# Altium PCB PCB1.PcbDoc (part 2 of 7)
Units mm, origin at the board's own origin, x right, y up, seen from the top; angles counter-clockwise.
Board outline 139.9 x 46.81 mm, 2 copper layers (Top Layer, Bottom Layer); 0 components, 100 nets, 100 pads, 0 vias.
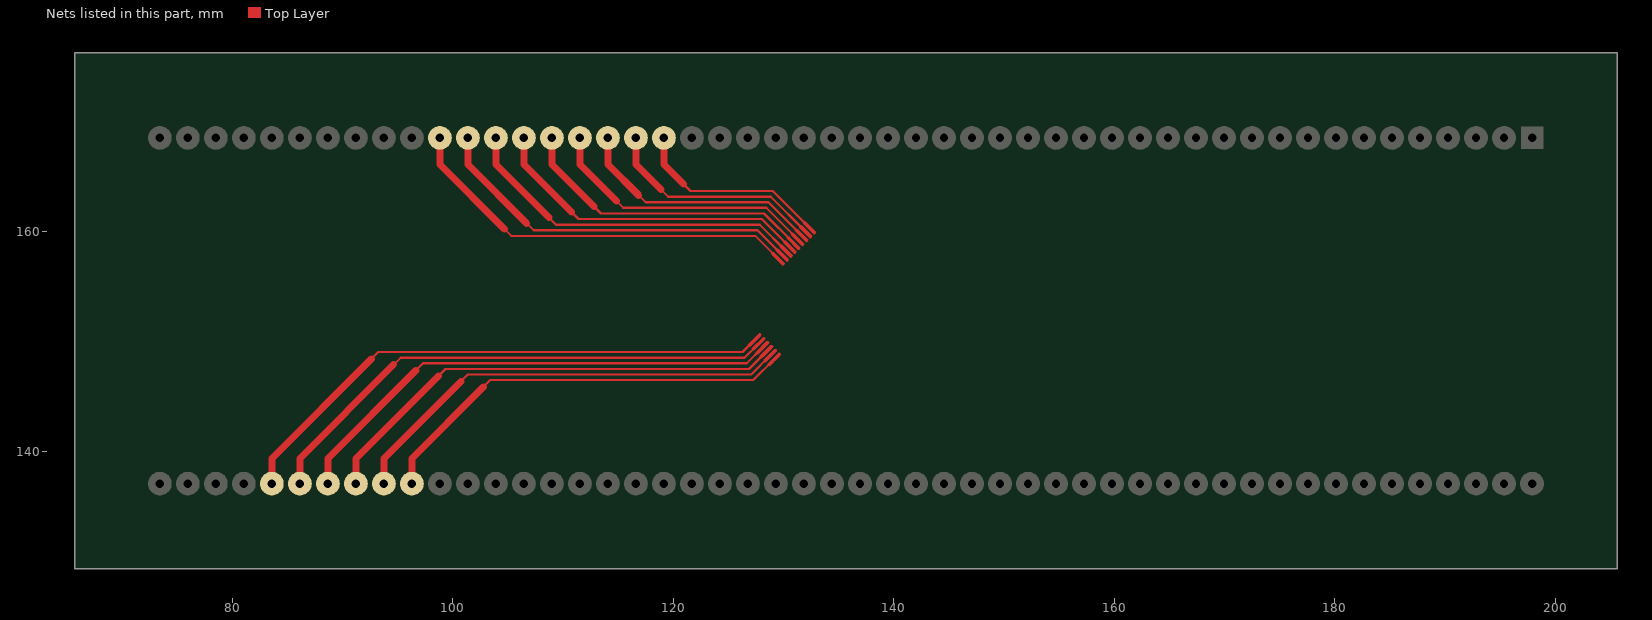
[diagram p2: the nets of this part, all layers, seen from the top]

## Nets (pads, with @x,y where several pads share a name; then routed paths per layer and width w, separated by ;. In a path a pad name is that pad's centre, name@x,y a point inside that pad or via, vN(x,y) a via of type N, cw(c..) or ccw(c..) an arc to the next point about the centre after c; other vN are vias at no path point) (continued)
$Net14: pad.1@83.587,137.086 | length 74.5
  Top Layer w0.03: 126.815,149.679 127.072,149.679 ; 126.815,149.694 127.087,149.694 ; 126.818,149.71 127.102,149.71 ; 126.82,149.664 127.057,149.664 ; 126.828,149.649 127.041,149.649 ; 126.838,149.633 127.026,149.633 ; 126.843,149.755 127.148,149.755 ; 126.851,149.618 127.011,149.618 ; 126.859,149.771 127.163,149.771 ; 126.866,149.603 126.996,149.603 ; 126.874,149.786 127.179,149.786 ; 126.889,149.588 126.978,149.588 ; 126.889,149.801 127.194,149.801 ; 126.904,149.816 127.209,149.816 ; 126.919,149.831 127.224,149.831 ; 126.935,149.847 127.24,149.847 ; 126.95,149.862 127.255,149.862 ; 126.965,149.877 127.27,149.877 ; 126.98,149.892 127.285,149.892 ; 126.996,149.908 127.3,149.908 ; 127.011,149.923 127.316,149.923 ; 127.026,149.938 127.331,149.938 ; 127.041,149.953 127.346,149.953 ; 127.057,149.969 127.361,149.969 ; 127.072,149.984 127.377,149.984 ; 127.087,149.999 127.392,149.999 ; 127.102,150.014 127.407,150.014 ; 127.118,149.725 126.82,149.725 ; 127.118,150.03 127.422,150.03 ; 127.133,149.74 126.828,149.74 ; 127.133,150.045 127.438,150.045 ; 127.148,150.06 127.455,150.06 ; 127.163,150.075 127.471,150.075 ; 127.179,150.091 127.486,150.091 ; 127.194,150.106 127.501,150.106 ; 127.209,150.121 127.516,150.121 ; 127.224,150.136 127.532,150.136 ; 127.24,150.152 127.547,150.152 ; 127.255,150.167 127.562,150.167 ; 127.27,150.182 127.577,150.182 ; 127.285,150.197 127.593,150.197 ; 127.3,150.212 127.608,150.212 ; 127.318,150.228 127.623,150.228 ; 127.334,150.243 127.638,150.243 ; 127.349,150.258 127.654,150.258 ; 127.364,150.273 127.669,150.273 ; 127.379,150.289 127.684,150.289 ; 127.394,150.304 127.699,150.304 ; 127.41,150.319 127.715,150.319 ; 127.425,150.334 127.73,150.334 ; 127.44,150.35 127.745,150.35 ; 127.455,150.365 127.76,150.365 ; 127.471,150.38 127.775,150.38 ; 127.486,150.395 127.791,150.395 ; 127.501,150.411 127.806,150.411 ; 127.516,150.426 127.821,150.426 ; 127.532,150.441 127.836,150.441 ; 127.547,150.456 127.852,150.456 ; 127.562,150.472 127.867,150.472 ; 127.577,150.487 127.882,150.487 ; 127.593,150.502 127.897,150.502 ; 127.608,150.517 127.913,150.517 ; 127.623,150.533 127.928,150.533 ; 127.638,150.548 127.938,150.548 ; 127.654,150.563 127.946,150.563 ; 127.669,150.578 127.948,150.578 ; 127.684,150.593 127.951,150.593 ; 127.699,150.609 127.948,150.609 ; 127.715,150.624 127.943,150.624 ; 127.73,150.639 127.933,150.639 ; 127.745,150.654 127.923,150.654 ; 127.76,150.67 127.908,150.67 ; 127.775,150.685 127.892,150.685 ; 127.796,150.7 127.869,150.7 ; 126.82,149.725 126.828,149.74 ; 126.82,149.725 126.813,149.692 126.815,149.674 126.82,149.659 126.841,149.628 126.869,149.6 126.899,149.58 126.914,149.575 126.932,149.572 126.965,149.58 126.978,149.588 ; 126.828,149.74 126.838,149.753 127.786,150.695 127.798,150.703 127.831,150.71 127.849,150.708 127.864,150.703 127.895,150.682 127.923,150.654 ; 126.978,149.588 127.925,150.53 127.935,150.543 127.943,150.558 127.951,150.591 127.948,150.609 ; 127.923,150.654 127.943,150.624 ; 127.943,150.624 127.948,150.609
  Top Layer w0.203: 92.604,148.389 93.239,149.024 126.264,149.024 127.382,150.141
  Top Layer w0.635: pad.1@83.587,137.086 83.587,139.372 92.604,148.389
$Net15: pad.1@86.127,137.086 | length 72.1
  Top Layer w0.03: 127.171,149.323 127.427,149.323 ; 127.171,149.339 127.443,149.339 ; 127.173,149.354 127.458,149.354 ; 127.176,149.308 127.412,149.308 ; 127.184,149.293 127.397,149.293 ; 127.194,149.278 127.382,149.278 ; 127.199,149.4 127.504,149.4 ; 127.207,149.263 127.367,149.263 ; 127.214,149.415 127.519,149.415 ; 127.222,149.247 127.351,149.247 ; 127.229,149.43 127.534,149.43 ; 127.245,149.232 127.334,149.232 ; 127.245,149.445 127.549,149.445 ; 127.26,149.461 127.565,149.461 ; 127.275,149.476 127.58,149.476 ; 127.29,149.491 127.595,149.491 ; 127.306,149.506 127.61,149.506 ; 127.321,149.522 127.626,149.522 ; 127.336,149.537 127.641,149.537 ; 127.351,149.552 127.656,149.552 ; 127.367,149.567 127.671,149.567 ; 127.382,149.583 127.687,149.583 ; 127.397,149.598 127.702,149.598 ; 127.412,149.613 127.717,149.613 ; 127.427,149.628 127.732,149.628 ; 127.443,149.644 127.748,149.644 ; 127.458,149.659 127.763,149.659 ; 127.473,149.369 127.176,149.369 ; 127.473,149.674 127.778,149.674 ; 127.488,149.384 127.184,149.384 ; 127.488,149.689 127.793,149.689 ; 127.504,149.704 127.811,149.704 ; 127.519,149.72 127.826,149.72 ; 127.534,149.735 127.842,149.735 ; 127.549,149.75 127.857,149.75 ; 127.565,149.765 127.872,149.765 ; 127.58,149.781 127.887,149.781 ; 127.595,149.796 127.902,149.796 ; 127.61,149.811 127.918,149.811 ; 127.626,149.826 127.933,149.826 ; 127.641,149.842 127.948,149.842 ; 127.656,149.857 127.963,149.857 ; 127.674,149.872 127.979,149.872 ; 127.689,149.887 127.994,149.887 ; 127.704,149.903 128.009,149.903 ; 127.72,149.918 128.024,149.918 ; 127.735,149.933 128.04,149.933 ; 127.75,149.948 128.055,149.948 ; 127.765,149.964 128.07,149.964 ; 127.781,149.979 128.085,149.979 ; 127.796,149.994 128.101,149.994 ; 127.811,150.009 128.116,150.009 ; 127.826,150.025 128.131,150.025 ; 127.842,150.04 128.146,150.04 ; 127.857,150.055 128.162,150.055 ; 127.872,150.07 128.177,150.07 ; 127.887,150.085 128.192,150.085 ; 127.902,150.101 128.207,150.101 ; 127.918,150.116 128.223,150.116 ; 127.933,150.131 128.238,150.131 ; 127.948,150.146 128.253,150.146 ; 127.963,150.162 128.268,150.162 ; 127.979,150.177 128.283,150.177 ; 127.994,150.192 128.294,150.192 ; 128.009,150.207 128.301,150.207 ; 128.024,150.223 128.304,150.223 ; 128.04,150.238 128.306,150.238 ; 128.055,150.253 128.304,150.253 ; 128.07,150.268 128.299,150.268 ; 128.085,150.284 128.289,150.284 ; 128.101,150.299 128.278,150.299 ; 128.116,150.314 128.263,150.314 ; 128.131,150.329 128.248,150.329 ; 128.151,150.345 128.225,150.345 ; 127.176,149.369 127.184,149.384 ; 127.176,149.369 127.168,149.336 127.171,149.318 127.176,149.303 127.196,149.273 127.224,149.245 127.255,149.224 127.27,149.219 127.288,149.217 127.321,149.224 127.334,149.232 ; 127.184,149.384 127.194,149.397 128.141,150.339 128.154,150.347 128.187,150.355 128.205,150.352 128.22,150.347 128.25,150.327 128.278,150.299 ; 127.334,149.232 128.281,150.174 128.291,150.187 128.299,150.202 128.306,150.235 128.304,150.253 ; 128.278,150.299 128.299,150.268 ; 128.299,150.268 128.304,150.253
  Top Layer w0.203: 94.636,147.881 95.271,148.516 126.465,148.516 127.737,149.786
  Top Layer w0.635: pad.1@86.127,137.086 86.127,139.372 94.636,147.881
$Net16: pad.1@88.667,137.086 | length 69.8
  Top Layer w0.03: 127.524,148.97 127.781,148.97 ; 127.524,148.986 127.796,148.986 ; 127.527,149.001 127.811,149.001 ; 127.529,148.955 127.765,148.955 ; 127.537,148.94 127.75,148.94 ; 127.547,148.925 127.735,148.925 ; 127.552,149.047 127.857,149.047 ; 127.56,148.909 127.72,148.909 ; 127.567,149.062 127.872,149.062 ; 127.575,148.894 127.704,148.894 ; 127.582,149.077 127.887,149.077 ; 127.598,148.879 127.687,148.879 ; 127.598,149.092 127.902,149.092 ; 127.613,149.108 127.918,149.108 ; 127.628,149.123 127.933,149.123 ; 127.643,149.138 127.948,149.138 ; 127.659,149.153 127.963,149.153 ; 127.674,149.169 127.979,149.169 ; 127.689,149.184 127.994,149.184 ; 127.704,149.199 128.009,149.199 ; 127.72,149.214 128.024,149.214 ; 127.735,149.229 128.04,149.229 ; 127.75,149.245 128.055,149.245 ; 127.765,149.26 128.07,149.26 ; 127.781,149.275 128.085,149.275 ; 127.796,149.29 128.101,149.29 ; 127.811,149.306 128.116,149.306 ; 127.826,149.016 127.529,149.016 ; 127.826,149.321 128.131,149.321 ; 127.842,149.031 127.537,149.031 ; 127.842,149.336 128.146,149.336 ; 127.857,149.351 128.164,149.351 ; 127.872,149.367 128.179,149.367 ; 127.887,149.382 128.195,149.382 ; 127.902,149.397 128.21,149.397 ; 127.918,149.412 128.225,149.412 ; 127.933,149.428 128.24,149.428 ; 127.948,149.443 128.256,149.443 ; 127.963,149.458 128.271,149.458 ; 127.979,149.473 128.286,149.473 ; 127.994,149.489 128.301,149.489 ; 128.009,149.504 128.316,149.504 ; 128.027,149.519 128.332,149.519 ; 128.042,149.534 128.347,149.534 ; 128.057,149.55 128.362,149.55 ; 128.073,149.565 128.377,149.565 ; 128.088,149.58 128.393,149.58 ; 128.103,149.595 128.408,149.595 ; 128.118,149.61 128.423,149.61 ; 128.134,149.626 128.438,149.626 ; 128.149,149.641 128.454,149.641 ; 128.164,149.656 128.469,149.656 ; 128.179,149.671 128.484,149.671 ; 128.195,149.687 128.499,149.687 ; 128.21,149.702 128.515,149.702 ; 128.225,149.717 128.53,149.717 ; 128.24,149.732 128.545,149.732 ; 128.256,149.748 128.56,149.748 ; 128.271,149.763 128.576,149.763 ; 128.286,149.778 128.591,149.778 ; 128.301,149.793 128.606,149.793 ; 128.316,149.809 128.621,149.809 ; 128.332,149.824 128.637,149.824 ; 128.347,149.839 128.647,149.839 ; 128.362,149.854 128.654,149.854 ; 128.377,149.87 128.657,149.87 ; 128.393,149.885 128.659,149.885 ; 128.408,149.9 128.657,149.9 ; 128.423,149.915 128.652,149.915 ; 128.438,149.931 128.642,149.931 ; 128.454,149.946 128.631,149.946 ; 128.469,149.961 128.616,149.961 ; 128.484,149.976 128.601,149.976 ; 128.504,149.991 128.578,149.991 ; 127.529,149.016 127.537,149.031 ; 127.529,149.016 127.521,148.983 127.524,148.965 127.529,148.95 127.549,148.92 127.577,148.892 127.608,148.871 127.623,148.866 127.641,148.864 127.674,148.871 127.687,148.879 ; 127.537,149.031 127.547,149.044 128.494,149.986 128.507,149.994 128.54,150.002 128.558,149.999 128.573,149.994 128.604,149.974 128.631,149.946 ; 127.687,148.879 128.634,149.821 128.644,149.834 128.652,149.849 128.659,149.882 128.657,149.9 ; 128.631,149.946 128.652,149.915 ; 128.652,149.915 128.657,149.9
  Top Layer w0.203: 96.668,147.373 97.303,148.008 126.663,148.008 128.09,149.433
  Top Layer w0.635: pad.1@88.667,137.086 88.667,139.372 96.668,147.373
$Net17: pad.1@91.207,137.086 | length 67.5
  Top Layer w0.03: 127.877,148.617 128.134,148.617 ; 127.877,148.633 128.149,148.633 ; 127.88,148.648 128.164,148.648 ; 127.882,148.602 128.118,148.602 ; 127.89,148.587 128.103,148.587 ; 127.9,148.572 128.088,148.572 ; 127.905,148.694 128.21,148.694 ; 127.913,148.556 128.073,148.556 ; 127.92,148.709 128.225,148.709 ; 127.928,148.541 128.057,148.541 ; 127.935,148.724 128.24,148.724 ; 127.951,148.526 128.04,148.526 ; 127.951,148.739 128.256,148.739 ; 127.966,148.755 128.271,148.755 ; 127.981,148.77 128.286,148.77 ; 127.996,148.785 128.301,148.785 ; 128.012,148.8 128.316,148.8 ; 128.027,148.815 128.332,148.815 ; 128.042,148.831 128.347,148.831 ; 128.057,148.846 128.362,148.846 ; 128.073,148.861 128.377,148.861 ; 128.088,148.876 128.393,148.876 ; 128.103,148.892 128.408,148.892 ; 128.118,148.907 128.423,148.907 ; 128.134,148.922 128.438,148.922 ; 128.149,148.937 128.454,148.937 ; 128.164,148.953 128.469,148.953 ; 128.179,148.663 127.882,148.663 ; 128.179,148.968 128.484,148.968 ; 128.195,148.678 127.89,148.678 ; 128.195,148.983 128.499,148.983 ; 128.21,148.998 128.517,148.998 ; 128.225,149.014 128.532,149.014 ; 128.24,149.029 128.548,149.029 ; 128.256,149.044 128.563,149.044 ; 128.271,149.059 128.578,149.059 ; 128.286,149.075 128.593,149.075 ; 128.301,149.09 128.609,149.09 ; 128.316,149.105 128.624,149.105 ; 128.332,149.12 128.639,149.12 ; 128.347,149.136 128.654,149.136 ; 128.362,149.151 128.67,149.151 ; 128.38,149.166 128.685,149.166 ; 128.395,149.181 128.7,149.181 ; 128.41,149.196 128.715,149.196 ; 128.426,149.212 128.731,149.212 ; 128.441,149.227 128.746,149.227 ; 128.456,149.242 128.761,149.242 ; 128.471,149.257 128.776,149.257 ; 128.487,149.273 128.791,149.273 ; 128.502,149.288 128.807,149.288 ; 128.517,149.303 128.822,149.303 ; 128.532,149.318 128.837,149.318 ; 128.548,149.334 128.852,149.334 ; 128.563,149.349 128.868,149.349 ; 128.578,149.364 128.883,149.364 ; 128.593,149.379 128.898,149.379 ; 128.609,149.395 128.913,149.395 ; 128.624,149.41 128.929,149.41 ; 128.639,149.425 128.944,149.425 ; 128.654,149.44 128.959,149.44 ; 128.67,149.456 128.974,149.456 ; 128.685,149.471 128.99,149.471 ; 128.7,149.486 129,149.486 ; 128.715,149.501 129.007,149.501 ; 128.731,149.517 129.01,149.517 ; 128.746,149.532 129.012,149.532 ; 128.761,149.547 129.01,149.547 ; 128.776,149.562 129.005,149.562 ; 128.791,149.577 128.995,149.577 ; 128.807,149.593 128.985,149.593 ; 128.822,149.608 128.969,149.608 ; 128.837,149.623 128.954,149.623 ; 128.858,149.638 128.931,149.638 ; 127.882,148.663 127.89,148.678 ; 127.882,148.663 127.875,148.63 127.877,148.612 127.882,148.597 127.902,148.567 127.93,148.539 127.961,148.518 127.976,148.513 127.994,148.511 128.027,148.518 128.04,148.526 ; 127.89,148.678 127.9,148.691 128.847,149.633 128.86,149.641 128.893,149.649 128.911,149.646 128.926,149.641 128.957,149.621 128.985,149.593 ; 128.04,148.526 128.987,149.468 128.997,149.481 129.005,149.496 129.012,149.529 129.01,149.547 ; 128.985,149.593 129.005,149.562 ; 129.005,149.562 129.01,149.547
  Top Layer w0.203: 98.7,146.865 99.335,147.5 126.864,147.5 128.443,149.08
  Top Layer w0.635: pad.1@91.207,137.086 91.207,139.372 98.7,146.865
$Net18: pad.1@93.747,137.086 | length 65.1
  Top Layer w0.03: 128.23,148.264 128.487,148.264 ; 128.23,148.28 128.502,148.28 ; 128.233,148.295 128.517,148.295 ; 128.235,148.249 128.471,148.249 ; 128.243,148.234 128.456,148.234 ; 128.253,148.219 128.441,148.219 ; 128.258,148.34 128.563,148.34 ; 128.266,148.203 128.426,148.203 ; 128.273,148.356 128.578,148.356 ; 128.281,148.188 128.41,148.188 ; 128.289,148.371 128.593,148.371 ; 128.304,148.173 128.393,148.173 ; 128.304,148.386 128.609,148.386 ; 128.319,148.401 128.624,148.401 ; 128.334,148.417 128.639,148.417 ; 128.35,148.432 128.654,148.432 ; 128.365,148.447 128.67,148.447 ; 128.38,148.462 128.685,148.462 ; 128.395,148.478 128.7,148.478 ; 128.41,148.493 128.715,148.493 ; 128.426,148.508 128.731,148.508 ; 128.441,148.523 128.746,148.523 ; 128.456,148.539 128.761,148.539 ; 128.471,148.554 128.776,148.554 ; 128.487,148.569 128.791,148.569 ; 128.502,148.584 128.807,148.584 ; 128.517,148.6 128.822,148.6 ; 128.532,148.31 128.235,148.31 ; 128.532,148.615 128.837,148.615 ; 128.548,148.325 128.243,148.325 ; 128.548,148.63 128.852,148.63 ; 128.563,148.645 128.87,148.645 ; 128.578,148.661 128.885,148.661 ; 128.593,148.676 128.901,148.676 ; 128.609,148.691 128.916,148.691 ; 128.624,148.706 128.931,148.706 ; 128.639,148.721 128.946,148.721 ; 128.654,148.737 128.962,148.737 ; 128.67,148.752 128.977,148.752 ; 128.685,148.767 128.992,148.767 ; 128.7,148.782 129.007,148.782 ; 128.715,148.798 129.023,148.798 ; 128.733,148.813 129.038,148.813 ; 128.748,148.828 129.053,148.828 ; 128.764,148.843 129.068,148.843 ; 128.779,148.859 129.084,148.859 ; 128.794,148.874 129.099,148.874 ; 128.809,148.889 129.114,148.889 ; 128.824,148.904 129.129,148.904 ; 128.84,148.92 129.145,148.92 ; 128.855,148.935 129.16,148.935 ; 128.87,148.95 129.175,148.95 ; 128.885,148.965 129.19,148.965 ; 128.901,148.981 129.205,148.981 ; 128.916,148.996 129.221,148.996 ; 128.931,149.011 129.236,149.011 ; 128.946,149.026 129.251,149.026 ; 128.962,149.042 129.266,149.042 ; 128.977,149.057 129.282,149.057 ; 128.992,149.072 129.297,149.072 ; 129.007,149.087 129.312,149.087 ; 129.023,149.102 129.327,149.102 ; 129.038,149.118 129.343,149.118 ; 129.053,149.133 129.353,149.133 ; 129.068,149.148 129.36,149.148 ; 129.084,149.163 129.363,149.163 ; 129.099,149.179 129.366,149.179 ; 129.114,149.194 129.363,149.194 ; 129.129,149.209 129.358,149.209 ; 129.145,149.224 129.348,149.224 ; 129.16,149.24 129.338,149.24 ; 129.175,149.255 129.322,149.255 ; 129.19,149.27 129.307,149.27 ; 129.211,149.285 129.284,149.285 ; 128.235,148.31 128.243,148.325 ; 128.235,148.31 128.228,148.277 128.23,148.259 128.235,148.244 128.256,148.213 128.283,148.186 128.314,148.165 128.329,148.16 128.347,148.158 128.38,148.165 128.393,148.173 ; 128.243,148.325 128.253,148.338 129.2,149.28 129.213,149.288 129.246,149.296 129.264,149.293 129.279,149.288 129.31,149.268 129.338,149.24 ; 128.393,148.173 129.34,149.115 129.35,149.128 129.358,149.143 129.366,149.176 129.363,149.194 ; 129.338,149.24 129.358,149.209 ; 129.358,149.209 129.363,149.194
  Top Layer w0.203: 100.732,146.357 101.367,146.992 127.062,146.992 128.797,148.727
  Top Layer w0.635: pad.1@93.747,137.086 93.747,139.372 100.732,146.357
$Net19: pad.1@96.287,137.086 | length 62.8
  Top Layer w0.03: 128.583,147.911 128.84,147.911 ; 128.583,147.926 128.855,147.926 ; 128.586,147.942 128.87,147.942 ; 128.588,147.896 128.824,147.896 ; 128.596,147.881 128.809,147.881 ; 128.606,147.866 128.794,147.866 ; 128.611,147.987 128.916,147.987 ; 128.619,147.85 128.779,147.85 ; 128.626,148.003 128.931,148.003 ; 128.634,147.835 128.764,147.835 ; 128.642,148.018 128.946,148.018 ; 128.657,147.82 128.746,147.82 ; 128.657,148.033 128.962,148.033 ; 128.672,148.048 128.977,148.048 ; 128.687,148.064 128.992,148.064 ; 128.703,148.079 129.007,148.079 ; 128.718,148.094 129.023,148.094 ; 128.733,148.109 129.038,148.109 ; 128.748,148.125 129.053,148.125 ; 128.764,148.14 129.068,148.14 ; 128.779,148.155 129.084,148.155 ; 128.794,148.17 129.099,148.17 ; 128.809,148.186 129.114,148.186 ; 128.824,148.201 129.129,148.201 ; 128.84,148.216 129.145,148.216 ; 128.855,148.231 129.16,148.231 ; 128.87,148.247 129.175,148.247 ; 128.885,147.957 128.588,147.957 ; 128.885,148.262 129.19,148.262 ; 128.901,147.972 128.596,147.972 ; 128.901,148.277 129.205,148.277 ; 128.916,148.292 129.223,148.292 ; 128.931,148.307 129.239,148.307 ; 128.946,148.323 129.254,148.323 ; 128.962,148.338 129.269,148.338 ; 128.977,148.353 129.284,148.353 ; 128.992,148.368 129.299,148.368 ; 129.007,148.384 129.315,148.384 ; 129.023,148.399 129.33,148.399 ; 129.038,148.414 129.345,148.414 ; 129.053,148.429 129.36,148.429 ; 129.068,148.445 129.376,148.445 ; 129.086,148.46 129.391,148.46 ; 129.101,148.475 129.406,148.475 ; 129.117,148.49 129.421,148.49 ; 129.132,148.506 129.437,148.506 ; 129.147,148.521 129.452,148.521 ; 129.162,148.536 129.467,148.536 ; 129.178,148.551 129.482,148.551 ; 129.193,148.567 129.498,148.567 ; 129.208,148.582 129.513,148.582 ; 129.223,148.597 129.528,148.597 ; 129.239,148.612 129.543,148.612 ; 129.254,148.628 129.559,148.628 ; 129.269,148.643 129.574,148.643 ; 129.284,148.658 129.589,148.658 ; 129.299,148.673 129.604,148.673 ; 129.315,148.688 129.62,148.688 ; 129.33,148.704 129.635,148.704 ; 129.345,148.719 129.65,148.719 ; 129.36,148.734 129.665,148.734 ; 129.376,148.749 129.68,148.749 ; 129.391,148.765 129.696,148.765 ; 129.406,148.78 129.706,148.78 ; 129.421,148.795 129.713,148.795 ; 129.437,148.81 129.716,148.81 ; 129.452,148.826 129.719,148.826 ; 129.467,148.841 129.716,148.841 ; 129.482,148.856 129.711,148.856 ; 129.498,148.871 129.701,148.871 ; 129.513,148.887 129.691,148.887 ; 129.528,148.902 129.675,148.902 ; 129.543,148.917 129.66,148.917 ; 129.564,148.932 129.637,148.932 ; 128.588,147.957 128.596,147.972 ; 128.588,147.957 128.581,147.924 128.583,147.906 128.588,147.891 128.609,147.86 128.637,147.832 128.667,147.812 128.682,147.807 128.7,147.805 128.733,147.812 128.746,147.82 ; 128.596,147.972 128.606,147.985 129.553,148.927 129.566,148.935 129.599,148.942 129.617,148.94 129.632,148.935 129.663,148.915 129.691,148.887 ; 128.746,147.82 129.693,148.762 129.703,148.775 129.711,148.79 129.719,148.823 129.716,148.841 ; 129.691,148.887 129.711,148.856 ; 129.711,148.856 129.716,148.841
  Top Layer w0.203: 102.764,145.849 103.399,146.484 127.26,146.484 129.15,148.374
  Top Layer w0.635: pad.1@96.287,137.086 96.287,139.372 102.764,145.849
$Net20: pad.1@98.827,168.455 | length 60.5
  Top Layer w0.03: 128.939,157.947 129.208,157.947 ; 128.941,157.932 129.223,157.932 ; 128.944,157.916 129.239,157.916 ; 128.951,157.901 129.254,157.901 ; 128.954,157.992 129.162,157.992 ; 128.964,157.886 129.269,157.886 ; 128.979,157.871 129.284,157.871 ; 128.979,158.023 129.132,158.023 ; 128.995,157.855 129.299,157.855 ; 128.997,158.038 129.117,158.038 ; 129.01,157.84 129.315,157.84 ; 129.02,158.053 129.094,158.053 ; 129.025,157.825 129.33,157.825 ; 129.04,157.81 129.345,157.81 ; 129.056,157.794 129.36,157.794 ; 129.071,157.779 129.376,157.779 ; 129.086,157.764 129.391,157.764 ; 129.101,157.749 129.406,157.749 ; 129.117,157.733 129.421,157.733 ; 129.132,157.718 129.437,157.718 ; 129.147,157.703 129.452,157.703 ; 129.147,158.008 128.964,158.008 ; 129.162,157.688 129.467,157.688 ; 129.178,157.672 129.482,157.672 ; 129.178,157.977 128.944,157.977 ; 129.193,157.657 129.498,157.657 ; 129.193,157.962 128.939,157.962 ; 129.208,157.642 129.513,157.642 ; 129.223,157.627 129.528,157.627 ; 129.239,157.611 129.543,157.611 ; 129.254,157.596 129.559,157.596 ; 129.269,157.581 129.574,157.581 ; 129.284,157.566 129.589,157.566 ; 129.299,157.551 129.602,157.551 ; 129.315,157.535 129.617,157.535 ; 129.33,157.52 129.632,157.52 ; 129.345,157.505 129.647,157.505 ; 129.36,157.49 129.663,157.49 ; 129.376,157.474 129.678,157.474 ; 129.391,157.459 129.693,157.459 ; 129.406,157.444 129.708,157.444 ; 129.421,157.429 129.724,157.429 ; 129.434,157.413 129.739,157.413 ; 129.449,157.398 129.754,157.398 ; 129.465,157.383 129.769,157.383 ; 129.48,157.368 129.785,157.368 ; 129.495,157.352 129.8,157.352 ; 129.51,157.337 129.815,157.337 ; 129.526,157.322 129.83,157.322 ; 129.541,157.307 129.846,157.307 ; 129.556,157.291 129.861,157.291 ; 129.571,157.276 129.876,157.276 ; 129.586,157.261 129.891,157.261 ; 129.602,157.246 129.907,157.246 ; 129.617,157.23 129.922,157.23 ; 129.632,157.215 129.937,157.215 ; 129.647,157.2 129.952,157.2 ; 129.663,157.185 129.967,157.185 ; 129.678,157.17 129.983,157.17 ; 129.693,157.154 129.998,157.154 ; 129.708,157.139 130.013,157.139 ; 129.724,157.124 130.028,157.124 ; 129.739,157.109 130.044,157.109 ; 129.754,157.093 130.059,157.093 ; 129.769,157.078 130.067,157.078 ; 129.785,157.063 130.072,157.063 ; 129.8,157.048 130.074,157.048 ; 129.815,157.032 130.074,157.032 ; 129.83,157.017 130.069,157.017 ; 129.846,157.002 130.061,157.002 ; 129.861,156.987 130.051,156.987 ; 129.876,156.971 130.036,156.971 ; 129.891,156.956 130.021,156.956 ; 130.001,156.941 129.907,156.941 ; 128.939,157.962 128.944,157.977 ; 128.939,157.962 128.936,157.944 128.944,157.911 128.951,157.899 129.894,156.951 129.907,156.941 ; 128.944,157.977 128.964,158.008 ; 128.964,158.008 128.992,158.036 129.023,158.056 129.038,158.061 129.056,158.064 129.089,158.056 129.104,158.048 129.117,158.038 ; 129.117,158.038 130.059,157.091 130.067,157.078 ; 129.907,156.941 129.922,156.933 129.955,156.926 129.973,156.928 129.988,156.933 130.018,156.954 130.046,156.982 130.067,157.012 130.072,157.027 130.074,157.045 130.067,157.078
  Top Layer w0.203: 104.669,160.2 105.304,159.565 127.435,159.565 129.505,157.495
  Top Layer w0.635: pad.1@98.827,168.455 98.827,166.042 104.669,160.2
$Net21: pad.1@101.367,168.455 | length 58.2
  Top Layer w0.03: 129.292,158.3 129.561,158.3 ; 129.294,158.285 129.576,158.285 ; 129.297,158.269 129.592,158.269 ; 129.305,158.254 129.607,158.254 ; 129.307,158.346 129.515,158.346 ; 129.317,158.239 129.622,158.239 ; 129.332,158.224 129.637,158.224 ; 129.332,158.376 129.485,158.376 ; 129.348,158.208 129.653,158.208 ; 129.35,158.391 129.47,158.391 ; 129.363,158.193 129.668,158.193 ; 129.373,158.407 129.447,158.407 ; 129.378,158.178 129.683,158.178 ; 129.393,158.163 129.698,158.163 ; 129.409,158.147 129.713,158.147 ; 129.424,158.132 129.729,158.132 ; 129.439,158.117 129.744,158.117 ; 129.454,158.102 129.759,158.102 ; 129.47,158.086 129.774,158.086 ; 129.485,158.071 129.79,158.071 ; 129.5,158.056 129.805,158.056 ; 129.5,158.361 129.317,158.361 ; 129.515,158.041 129.82,158.041 ; 129.531,158.026 129.835,158.026 ; 129.531,158.33 129.297,158.33 ; 129.546,158.01 129.851,158.01 ; 129.546,158.315 129.292,158.315 ; 129.561,157.995 129.866,157.995 ; 129.576,157.98 129.881,157.98 ; 129.592,157.965 129.896,157.965 ; 129.607,157.949 129.912,157.949 ; 129.622,157.934 129.927,157.934 ; 129.637,157.919 129.942,157.919 ; 129.653,157.904 129.955,157.904 ; 129.668,157.888 129.97,157.888 ; 129.683,157.873 129.985,157.873 ; 129.698,157.858 130.001,157.858 ; 129.713,157.843 130.016,157.843 ; 129.729,157.827 130.031,157.827 ; 129.744,157.812 130.046,157.812 ; 129.759,157.797 130.061,157.797 ; 129.774,157.782 130.077,157.782 ; 129.787,157.766 130.092,157.766 ; 129.802,157.751 130.107,157.751 ; 129.818,157.736 130.122,157.736 ; 129.833,157.721 130.138,157.721 ; 129.848,157.705 130.153,157.705 ; 129.863,157.69 130.168,157.69 ; 129.879,157.675 130.183,157.675 ; 129.894,157.66 130.199,157.66 ; 129.909,157.645 130.214,157.645 ; 129.924,157.629 130.229,157.629 ; 129.94,157.614 130.244,157.614 ; 129.955,157.599 130.26,157.599 ; 129.97,157.584 130.275,157.584 ; 129.985,157.568 130.29,157.568 ; 130.001,157.553 130.305,157.553 ; 130.016,157.538 130.321,157.538 ; 130.031,157.523 130.336,157.523 ; 130.046,157.507 130.351,157.507 ; 130.061,157.492 130.366,157.492 ; 130.077,157.477 130.382,157.477 ; 130.092,157.462 130.397,157.462 ; 130.107,157.446 130.412,157.446 ; 130.122,157.431 130.42,157.431 ; 130.138,157.416 130.425,157.416 ; 130.153,157.401 130.427,157.401 ; 130.168,157.385 130.427,157.385 ; 130.183,157.37 130.422,157.37 ; 130.199,157.355 130.415,157.355 ; 130.214,157.34 130.404,157.34 ; 130.229,157.324 130.389,157.324 ; 130.244,157.309 130.374,157.309 ; 130.354,157.294 130.26,157.294 ; 129.292,158.315 129.297,158.33 ; 129.292,158.315 129.289,158.297 129.297,158.264 129.305,158.252 130.247,157.304 130.26,157.294 ; 129.297,158.33 129.317,158.361 ; 129.317,158.361 129.345,158.389 129.376,158.409 129.391,158.414 129.409,158.417 129.442,158.409 129.457,158.401 129.47,158.391 ; 129.47,158.391 130.412,157.444 130.42,157.431 ; 130.26,157.294 130.275,157.286 130.308,157.279 130.326,157.281 130.341,157.286 130.371,157.307 130.399,157.335 130.42,157.365 130.425,157.38 130.427,157.398 130.42,157.431
  Top Layer w0.203: 106.701,160.708 107.336,160.073 127.633,160.073 129.858,157.848
  Top Layer w0.635: pad.1@101.367,168.455 101.367,166.042 106.701,160.708
$Net22: pad.1@103.907,168.455 | length 55.9
  Top Layer w0.03: 129.645,158.653 129.914,158.653 ; 129.647,158.638 129.929,158.638 ; 129.65,158.622 129.945,158.622 ; 129.658,158.607 129.96,158.607 ; 129.66,158.699 129.868,158.699 ; 129.67,158.592 129.975,158.592 ; 129.686,158.577 129.99,158.577 ; 129.686,158.729 129.838,158.729 ; 129.701,158.561 130.006,158.561 ; 129.703,158.744 129.823,158.744 ; 129.716,158.546 130.021,158.546 ; 129.726,158.76 129.8,158.76 ; 129.731,158.531 130.036,158.531 ; 129.747,158.516 130.051,158.516 ; 129.762,158.5 130.067,158.5 ; 129.777,158.485 130.082,158.485 ; 129.792,158.47 130.097,158.47 ; 129.807,158.455 130.112,158.455 ; 129.823,158.44 130.128,158.44 ; 129.838,158.424 130.143,158.424 ; 129.853,158.409 130.158,158.409 ; 129.853,158.714 129.67,158.714 ; 129.868,158.394 130.173,158.394 ; 129.884,158.379 130.188,158.379 ; 129.884,158.683 129.65,158.683 ; 129.899,158.363 130.204,158.363 ; 129.899,158.668 129.645,158.668 ; 129.914,158.348 130.219,158.348 ; 129.929,158.333 130.234,158.333 ; 129.945,158.318 130.249,158.318 ; 129.96,158.302 130.265,158.302 ; 129.975,158.287 130.28,158.287 ; 129.99,158.272 130.295,158.272 ; 130.006,158.257 130.308,158.257 ; 130.021,158.241 130.323,158.241 ; 130.036,158.226 130.338,158.226 ; 130.051,158.211 130.354,158.211 ; 130.067,158.196 130.369,158.196 ; 130.082,158.18 130.384,158.18 ; 130.097,158.165 130.399,158.165 ; 130.112,158.15 130.415,158.15 ; 130.128,158.135 130.43,158.135 ; 130.14,158.119 130.445,158.119 ; 130.155,158.104 130.46,158.104 ; 130.171,158.089 130.475,158.089 ; 130.186,158.074 130.491,158.074 ; 130.201,158.059 130.506,158.059 ; 130.216,158.043 130.521,158.043 ; 130.232,158.028 130.536,158.028 ; 130.247,158.013 130.552,158.013 ; 130.262,157.998 130.567,157.998 ; 130.277,157.982 130.582,157.982 ; 130.293,157.967 130.597,157.967 ; 130.308,157.952 130.613,157.952 ; 130.323,157.937 130.628,157.937 ; 130.338,157.921 130.643,157.921 ; 130.354,157.906 130.658,157.906 ; 130.369,157.891 130.674,157.891 ; 130.384,157.876 130.689,157.876 ; 130.399,157.86 130.704,157.86 ; 130.415,157.845 130.719,157.845 ; 130.43,157.83 130.735,157.83 ; 130.445,157.815 130.75,157.815 ; 130.46,157.799 130.765,157.799 ; 130.475,157.784 130.773,157.784 ; 130.491,157.769 130.778,157.769 ; 130.506,157.754 130.78,157.754 ; 130.521,157.738 130.78,157.738 ; 130.536,157.723 130.775,157.723 ; 130.552,157.708 130.768,157.708 ; 130.567,157.693 130.757,157.693 ; 130.582,157.678 130.742,157.678 ; 130.597,157.662 130.727,157.662 ; 130.707,157.647 130.613,157.647 ; 129.645,158.668 129.65,158.683 ; 129.645,158.668 129.642,158.65 129.65,158.617 129.658,158.605 130.6,157.657 130.613,157.647 ; 129.65,158.683 129.67,158.714 ; 129.67,158.714 129.698,158.742 129.729,158.762 129.744,158.767 129.762,158.77 129.795,158.762 129.81,158.754 129.823,158.744 ; 129.823,158.744 130.765,157.797 130.773,157.784 ; 130.613,157.647 130.628,157.639 130.661,157.632 130.679,157.634 130.694,157.639 130.724,157.66 130.752,157.688 130.773,157.718 130.778,157.733 130.78,157.751 130.773,157.784
  Top Layer w0.203: 108.733,161.216 109.368,160.581 127.834,160.581 130.211,158.201
  Top Layer w0.635: pad.1@103.907,168.455 103.907,166.042 108.733,161.216
$Net23: pad.1@106.447,168.455 | length 53.5
  Top Layer w0.03: 129.998,159.006 130.267,159.006 ; 130.001,158.991 130.282,158.991 ; 130.003,158.975 130.298,158.975 ; 130.011,158.96 130.313,158.96 ; 130.013,159.052 130.221,159.052 ; 130.023,158.945 130.328,158.945 ; 130.039,158.93 130.343,158.93 ; 130.039,159.082 130.191,159.082 ; 130.054,158.915 130.359,158.915 ; 130.056,159.097 130.176,159.097 ; 130.069,158.899 130.374,158.899 ; 130.079,159.113 130.153,159.113 ; 130.084,158.884 130.389,158.884 ; 130.1,158.869 130.404,158.869 ; 130.115,158.854 130.42,158.854 ; 130.13,158.838 130.435,158.838 ; 130.145,158.823 130.45,158.823 ; 130.161,158.808 130.465,158.808 ; 130.176,158.793 130.481,158.793 ; 130.191,158.777 130.496,158.777 ; 130.206,158.762 130.511,158.762 ; 130.206,159.067 130.023,159.067 ; 130.221,158.747 130.526,158.747 ; 130.237,158.732 130.542,158.732 ; 130.237,159.036 130.003,159.036 ; 130.252,158.716 130.557,158.716 ; 130.252,159.021 129.998,159.021 ; 130.267,158.701 130.572,158.701 ; 130.282,158.686 130.587,158.686 ; 130.298,158.671 130.602,158.671 ; 130.313,158.655 130.618,158.655 ; 130.328,158.64 130.633,158.64 ; 130.343,158.625 130.648,158.625 ; 130.359,158.61 130.661,158.61 ; 130.374,158.594 130.676,158.594 ; 130.389,158.579 130.691,158.579 ; 130.404,158.564 130.707,158.564 ; 130.42,158.549 130.722,158.549 ; 130.435,158.534 130.737,158.534 ; 130.45,158.518 130.752,158.518 ; 130.465,158.503 130.768,158.503 ; 130.481,158.488 130.783,158.488 ; 130.493,158.473 130.798,158.473 ; 130.509,158.457 130.813,158.457 ; 130.524,158.442 130.829,158.442 ; 130.539,158.427 130.844,158.427 ; 130.554,158.412 130.859,158.412 ; 130.569,158.396 130.874,158.396 ; 130.585,158.381 130.89,158.381 ; 130.6,158.366 130.905,158.366 ; 130.615,158.351 130.92,158.351 ; 130.63,158.335 130.935,158.335 ; 130.646,158.32 130.95,158.32 ; 130.661,158.305 130.966,158.305 ; 130.676,158.29 130.981,158.29 ; 130.691,158.274 130.996,158.274 ; 130.707,158.259 131.011,158.259 ; 130.722,158.244 131.027,158.244 ; 130.737,158.229 131.042,158.229 ; 130.752,158.213 131.057,158.213 ; 130.768,158.198 131.072,158.198 ; 130.783,158.183 131.088,158.183 ; 130.798,158.168 131.103,158.168 ; 130.813,158.153 131.118,158.153 ; 130.829,158.137 131.126,158.137 ; 130.844,158.122 131.131,158.122 ; 130.859,158.107 131.133,158.107 ; 130.874,158.092 131.133,158.092 ; 130.89,158.076 131.128,158.076 ; 130.905,158.061 131.121,158.061 ; 130.92,158.046 131.11,158.046 ; 130.935,158.031 131.095,158.031 ; 130.95,158.015 131.08,158.015 ; 131.06,158 130.966,158 ; 129.998,159.021 130.003,159.036 ; 129.998,159.021 129.995,159.003 130.003,158.97 130.011,158.958 130.953,158.01 130.966,158 ; 130.003,159.036 130.023,159.067 ; 130.023,159.067 130.051,159.095 130.082,159.115 130.097,159.12 130.115,159.123 130.148,159.115 130.163,159.108 130.176,159.097 ; 130.176,159.097 131.118,158.15 131.126,158.137 ; 130.966,158 130.981,157.992 131.014,157.985 131.032,157.987 131.047,157.992 131.077,158.013 131.105,158.041 131.126,158.071 131.131,158.086 131.133,158.104 131.126,158.137
  Top Layer w0.203: 110.765,161.724 111.4,161.089 128.032,161.089 130.564,158.554
  Top Layer w0.635: pad.1@106.447,168.455 106.447,166.042 110.765,161.724
$Net24: pad.1@108.987,168.455 | length 51.2
  Top Layer w0.03: 130.351,159.362 130.62,159.362 ; 130.354,159.346 130.636,159.346 ; 130.356,159.331 130.651,159.331 ; 130.364,159.316 130.666,159.316 ; 130.366,159.407 130.575,159.407 ; 130.376,159.301 130.681,159.301 ; 130.392,159.285 130.696,159.285 ; 130.392,159.438 130.544,159.438 ; 130.407,159.27 130.712,159.27 ; 130.409,159.453 130.529,159.453 ; 130.422,159.255 130.727,159.255 ; 130.432,159.468 130.506,159.468 ; 130.437,159.24 130.742,159.24 ; 130.453,159.224 130.757,159.224 ; 130.468,159.209 130.773,159.209 ; 130.483,159.194 130.788,159.194 ; 130.498,159.179 130.803,159.179 ; 130.514,159.163 130.818,159.163 ; 130.529,159.148 130.834,159.148 ; 130.544,159.133 130.849,159.133 ; 130.559,159.118 130.864,159.118 ; 130.559,159.423 130.376,159.423 ; 130.575,159.102 130.879,159.102 ; 130.59,159.087 130.895,159.087 ; 130.59,159.392 130.356,159.392 ; 130.605,159.072 130.91,159.072 ; 130.605,159.377 130.351,159.377 ; 130.62,159.057 130.925,159.057 ; 130.636,159.042 130.94,159.042 ; 130.651,159.026 130.956,159.026 ; 130.666,159.011 130.971,159.011 ; 130.681,158.996 130.986,158.996 ; 130.696,158.981 131.001,158.981 ; 130.712,158.965 131.014,158.965 ; 130.727,158.95 131.029,158.95 ; 130.742,158.935 131.044,158.935 ; 130.757,158.92 131.06,158.92 ; 130.773,158.904 131.075,158.904 ; 130.788,158.889 131.09,158.889 ; 130.803,158.874 131.105,158.874 ; 130.818,158.859 131.121,158.859 ; 130.834,158.843 131.136,158.843 ; 130.846,158.828 131.151,158.828 ; 130.862,158.813 131.166,158.813 ; 130.877,158.798 131.182,158.798 ; 130.892,158.782 131.197,158.782 ; 130.907,158.767 131.212,158.767 ; 130.923,158.752 131.227,158.752 ; 130.938,158.737 131.243,158.737 ; 130.953,158.721 131.258,158.721 ; 130.968,158.706 131.273,158.706 ; 130.983,158.691 131.288,158.691 ; 130.999,158.676 131.304,158.676 ; 131.014,158.661 131.319,158.661 ; 131.029,158.645 131.334,158.645 ; 131.044,158.63 131.349,158.63 ; 131.06,158.615 131.364,158.615 ; 131.075,158.6 131.38,158.6 ; 131.09,158.584 131.395,158.584 ; 131.105,158.569 131.41,158.569 ; 131.121,158.554 131.425,158.554 ; 131.136,158.539 131.441,158.539 ; 131.151,158.523 131.456,158.523 ; 131.166,158.508 131.471,158.508 ; 131.182,158.493 131.479,158.493 ; 131.197,158.478 131.484,158.478 ; 131.212,158.462 131.486,158.462 ; 131.227,158.447 131.486,158.447 ; 131.243,158.432 131.481,158.432 ; 131.258,158.417 131.474,158.417 ; 131.273,158.401 131.464,158.401 ; 131.288,158.386 131.448,158.386 ; 131.304,158.371 131.433,158.371 ; 131.413,158.356 131.319,158.356 ; 130.351,159.377 130.356,159.392 ; 130.351,159.377 130.348,159.359 130.356,159.326 130.364,159.313 131.306,158.366 131.319,158.356 ; 130.356,159.392 130.376,159.423 ; 130.376,159.423 130.404,159.45 130.435,159.471 130.45,159.476 130.468,159.478 130.501,159.471 130.516,159.463 130.529,159.453 ; 130.529,159.453 131.471,158.506 131.479,158.493 ; 131.319,158.356 131.334,158.348 131.367,158.34 131.385,158.343 131.4,158.348 131.431,158.368 131.458,158.396 131.479,158.427 131.484,158.442 131.486,158.46 131.479,158.493
  Top Layer w0.203: 112.797,162.232 113.432,161.597 128.23,161.597 130.917,158.909
  Top Layer w0.635: pad.1@108.987,168.455 108.987,166.042 112.797,162.232
$Net25: pad.1@111.527,168.455 | length 48.9
  Top Layer w0.03: 130.707,159.715 130.976,159.715 ; 130.709,159.699 130.991,159.699 ; 130.712,159.684 131.006,159.684 ; 130.719,159.669 131.022,159.669 ; 130.722,159.76 130.93,159.76 ; 130.732,159.654 131.037,159.654 ; 130.747,159.638 131.052,159.638 ; 130.747,159.791 130.9,159.791 ; 130.763,159.623 131.067,159.623 ; 130.765,159.806 130.884,159.806 ; 130.778,159.608 131.083,159.608 ; 130.788,159.821 130.862,159.821 ; 130.793,159.593 131.098,159.593 ; 130.808,159.577 131.113,159.577 ; 130.823,159.562 131.128,159.562 ; 130.839,159.547 131.144,159.547 ; 130.854,159.532 131.159,159.532 ; 130.869,159.516 131.174,159.516 ; 130.884,159.501 131.189,159.501 ; 130.9,159.486 131.204,159.486 ; 130.915,159.471 131.22,159.471 ; 130.915,159.776 130.732,159.776 ; 130.93,159.456 131.235,159.456 ; 130.945,159.44 131.25,159.44 ; 130.945,159.745 130.712,159.745 ; 130.961,159.425 131.265,159.425 ; 130.961,159.73 130.707,159.73 ; 130.976,159.41 131.281,159.41 ; 130.991,159.395 131.296,159.395 ; 131.006,159.379 131.311,159.379 ; 131.022,159.364 131.326,159.364 ; 131.037,159.349 131.342,159.349 ; 131.052,159.334 131.357,159.334 ; 131.067,159.318 131.37,159.318 ; 131.083,159.303 131.385,159.303 ; 131.098,159.288 131.4,159.288 ; 131.113,159.273 131.415,159.273 ; 131.128,159.257 131.431,159.257 ; 131.144,159.242 131.446,159.242 ; 131.159,159.227 131.461,159.227 ; 131.174,159.212 131.476,159.212 ; 131.189,159.196 131.491,159.196 ; 131.202,159.181 131.507,159.181 ; 131.217,159.166 131.522,159.166 ; 131.232,159.151 131.537,159.151 ; 131.248,159.135 131.552,159.135 ; 131.263,159.12 131.568,159.12 ; 131.278,159.105 131.583,159.105 ; 131.293,159.09 131.598,159.09 ; 131.309,159.075 131.613,159.075 ; 131.324,159.059 131.629,159.059 ; 131.339,159.044 131.644,159.044 ; 131.354,159.029 131.659,159.029 ; 131.37,159.014 131.674,159.014 ; 131.385,158.998 131.69,158.998 ; 131.4,158.983 131.705,158.983 ; 131.415,158.968 131.72,158.968 ; 131.431,158.953 131.735,158.953 ; 131.446,158.937 131.751,158.937 ; 131.461,158.922 131.766,158.922 ; 131.476,158.907 131.781,158.907 ; 131.491,158.892 131.796,158.892 ; 131.507,158.876 131.812,158.876 ; 131.522,158.861 131.827,158.861 ; 131.537,158.846 131.834,158.846 ; 131.552,158.831 131.839,158.831 ; 131.568,158.815 131.842,158.815 ; 131.583,158.8 131.842,158.8 ; 131.598,158.785 131.837,158.785 ; 131.613,158.77 131.829,158.77 ; 131.629,158.754 131.819,158.754 ; 131.644,158.739 131.804,158.739 ; 131.659,158.724 131.789,158.724 ; 131.768,158.709 131.674,158.709 ; 130.707,159.73 130.712,159.745 ; 130.707,159.73 130.704,159.712 130.712,159.679 130.719,159.666 131.662,158.719 131.674,158.709 ; 130.712,159.745 130.732,159.776 ; 130.732,159.776 130.76,159.804 130.79,159.824 130.806,159.829 130.823,159.831 130.856,159.824 130.872,159.816 130.884,159.806 ; 130.884,159.806 131.827,158.859 131.834,158.846 ; 131.674,158.709 131.69,158.701 131.723,158.694 131.74,158.696 131.756,158.701 131.786,158.721 131.814,158.749 131.834,158.78 131.839,158.795 131.842,158.813 131.834,158.846
  Top Layer w0.203: 114.829,162.74 115.464,162.105 128.431,162.105 131.273,159.262
  Top Layer w0.635: pad.1@111.527,168.455 111.527,166.042 114.829,162.74
$Net26: pad.1@114.067,168.455 | length 46.6
  Top Layer w0.03: 131.06,160.068 131.329,160.068 ; 131.062,160.052 131.344,160.052 ; 131.065,160.037 131.359,160.037 ; 131.072,160.022 131.375,160.022 ; 131.075,160.113 131.283,160.113 ; 131.085,160.007 131.39,160.007 ; 131.1,159.991 131.405,159.991 ; 131.1,160.144 131.253,160.144 ; 131.116,159.976 131.42,159.976 ; 131.118,160.159 131.237,160.159 ; 131.131,159.961 131.436,159.961 ; 131.141,160.174 131.215,160.174 ; 131.146,159.946 131.451,159.946 ; 131.161,159.931 131.466,159.931 ; 131.177,159.915 131.481,159.915 ; 131.192,159.9 131.497,159.9 ; 131.207,159.885 131.512,159.885 ; 131.222,159.87 131.527,159.87 ; 131.237,159.854 131.542,159.854 ; 131.253,159.839 131.558,159.839 ; 131.268,159.824 131.573,159.824 ; 131.268,160.129 131.085,160.129 ; 131.283,159.809 131.588,159.809 ; 131.298,159.793 131.603,159.793 ; 131.298,160.098 131.065,160.098 ; 131.314,159.778 131.618,159.778 ; 131.314,160.083 131.06,160.083 ; 131.329,159.763 131.634,159.763 ; 131.344,159.748 131.649,159.748 ; 131.359,159.732 131.664,159.732 ; 131.375,159.717 131.679,159.717 ; 131.39,159.702 131.695,159.702 ; 131.405,159.687 131.71,159.687 ; 131.42,159.671 131.723,159.671 ; 131.436,159.656 131.738,159.656 ; 131.451,159.641 131.753,159.641 ; 131.466,159.626 131.768,159.626 ; 131.481,159.61 131.784,159.61 ; 131.497,159.595 131.799,159.595 ; 131.512,159.58 131.814,159.58 ; 131.527,159.565 131.829,159.565 ; 131.542,159.55 131.845,159.55 ; 131.555,159.534 131.86,159.534 ; 131.57,159.519 131.875,159.519 ; 131.585,159.504 131.89,159.504 ; 131.601,159.489 131.906,159.489 ; 131.616,159.473 131.921,159.473 ; 131.631,159.458 131.936,159.458 ; 131.646,159.443 131.951,159.443 ; 131.662,159.428 131.966,159.428 ; 131.677,159.412 131.982,159.412 ; 131.692,159.397 131.997,159.397 ; 131.707,159.382 132.012,159.382 ; 131.723,159.367 132.027,159.367 ; 131.738,159.351 132.043,159.351 ; 131.753,159.336 132.058,159.336 ; 131.768,159.321 132.073,159.321 ; 131.784,159.306 132.088,159.306 ; 131.799,159.29 132.104,159.29 ; 131.814,159.275 132.119,159.275 ; 131.829,159.26 132.134,159.26 ; 131.845,159.245 132.149,159.245 ; 131.86,159.229 132.165,159.229 ; 131.875,159.214 132.18,159.214 ; 131.89,159.199 132.187,159.199 ; 131.906,159.184 132.193,159.184 ; 131.921,159.169 132.195,159.169 ; 131.936,159.153 132.195,159.153 ; 131.951,159.138 132.19,159.138 ; 131.966,159.123 132.182,159.123 ; 131.982,159.108 132.172,159.108 ; 131.997,159.092 132.157,159.092 ; 132.012,159.077 132.142,159.077 ; 132.121,159.062 132.027,159.062 ; 131.06,160.083 131.065,160.098 ; 131.06,160.083 131.057,160.065 131.065,160.032 131.072,160.019 132.015,159.072 132.027,159.062 ; 131.065,160.098 131.085,160.129 ; 131.085,160.129 131.113,160.157 131.144,160.177 131.159,160.182 131.177,160.185 131.21,160.177 131.225,160.169 131.237,160.159 ; 131.237,160.159 132.18,159.212 132.187,159.199 ; 132.027,159.062 132.043,159.054 132.076,159.047 132.093,159.049 132.109,159.054 132.139,159.075 132.167,159.102 132.187,159.133 132.193,159.148 132.195,159.166 132.187,159.199
  Top Layer w0.203: 116.861,163.248 117.496,162.613 128.629,162.613 131.626,159.616
  Top Layer w0.635: pad.1@114.067,168.455 114.067,166.042 116.861,163.248
$Net27: pad.1@116.607,168.455 | length 44.2
  Top Layer w0.03: 131.413,160.421 131.682,160.421 ; 131.415,160.405 131.697,160.405 ; 131.418,160.39 131.712,160.39 ; 131.425,160.375 131.728,160.375 ; 131.428,160.466 131.636,160.466 ; 131.438,160.36 131.743,160.36 ; 131.453,160.345 131.758,160.345 ; 131.453,160.497 131.606,160.497 ; 131.469,160.329 131.773,160.329 ; 131.471,160.512 131.591,160.512 ; 131.484,160.314 131.789,160.314 ; 131.494,160.527 131.568,160.527 ; 131.499,160.299 131.804,160.299 ; 131.514,160.284 131.819,160.284 ; 131.53,160.268 131.834,160.268 ; 131.545,160.253 131.85,160.253 ; 131.56,160.238 131.865,160.238 ; 131.575,160.223 131.88,160.223 ; 131.591,160.207 131.895,160.207 ; 131.606,160.192 131.911,160.192 ; 131.621,160.177 131.926,160.177 ; 131.621,160.482 131.438,160.482 ; 131.636,160.162 131.941,160.162 ; 131.652,160.146 131.956,160.146 ; 131.652,160.451 131.418,160.451 ; 131.667,160.131 131.972,160.131 ; 131.667,160.436 131.413,160.436 ; 131.682,160.116 131.987,160.116 ; 131.697,160.101 132.002,160.101 ; 131.712,160.085 132.017,160.085 ; 131.728,160.07 132.033,160.07 ; 131.743,160.055 132.048,160.055 ; 131.758,160.04 132.063,160.04 ; 131.773,160.024 132.076,160.024 ; 131.789,160.009 132.091,160.009 ; 131.804,159.994 132.106,159.994 ; 131.819,159.979 132.121,159.979 ; 131.834,159.964 132.137,159.964 ; 131.85,159.948 132.152,159.948 ; 131.865,159.933 132.167,159.933 ; 131.88,159.918 132.182,159.918 ; 131.895,159.903 132.198,159.903 ; 131.908,159.887 132.213,159.887 ; 131.923,159.872 132.228,159.872 ; 131.939,159.857 132.243,159.857 ; 131.954,159.842 132.259,159.842 ; 131.969,159.826 132.274,159.826 ; 131.984,159.811 132.289,159.811 ; 131.999,159.796 132.304,159.796 ; 132.015,159.781 132.32,159.781 ; 132.03,159.765 132.335,159.765 ; 132.045,159.75 132.35,159.75 ; 132.06,159.735 132.365,159.735 ; 132.076,159.72 132.38,159.72 ; 132.091,159.704 132.396,159.704 ; 132.106,159.689 132.411,159.689 ; 132.121,159.674 132.426,159.674 ; 132.137,159.659 132.441,159.659 ; 132.152,159.643 132.457,159.643 ; 132.167,159.628 132.472,159.628 ; 132.182,159.613 132.487,159.613 ; 132.198,159.598 132.502,159.598 ; 132.213,159.583 132.518,159.583 ; 132.228,159.567 132.533,159.567 ; 132.243,159.552 132.541,159.552 ; 132.259,159.537 132.546,159.537 ; 132.274,159.522 132.548,159.522 ; 132.289,159.506 132.548,159.506 ; 132.304,159.491 132.543,159.491 ; 132.32,159.476 132.535,159.476 ; 132.335,159.461 132.525,159.461 ; 132.35,159.445 132.51,159.445 ; 132.365,159.43 132.495,159.43 ; 132.474,159.415 132.38,159.415 ; 131.413,160.436 131.418,160.451 ; 131.413,160.436 131.41,160.418 131.418,160.385 131.425,160.372 132.368,159.425 132.38,159.415 ; 131.418,160.451 131.438,160.482 ; 131.438,160.482 131.466,160.51 131.497,160.53 131.512,160.535 131.53,160.538 131.563,160.53 131.578,160.522 131.591,160.512 ; 131.591,160.512 132.533,159.565 132.541,159.552 ; 132.38,159.415 132.396,159.407 132.429,159.4 132.447,159.402 132.462,159.407 132.492,159.428 132.52,159.456 132.541,159.486 132.546,159.501 132.548,159.519 132.541,159.552
  Top Layer w0.203: 118.893,163.756 119.528,163.121 128.827,163.121 131.979,159.969
  Top Layer w0.635: pad.1@116.607,168.455 116.607,166.042 118.893,163.756
$Net28: pad.1@119.147,168.455 | length 41.9
  Top Layer w0.03: 131.766,160.774 132.035,160.774 ; 131.768,160.759 132.05,160.759 ; 131.771,160.743 132.066,160.743 ; 131.779,160.728 132.081,160.728 ; 131.781,160.82 131.989,160.82 ; 131.791,160.713 132.096,160.713 ; 131.806,160.698 132.111,160.698 ; 131.806,160.85 131.959,160.85 ; 131.822,160.682 132.126,160.682 ; 131.824,160.865 131.944,160.865 ; 131.837,160.667 132.142,160.667 ; 131.847,160.88 131.921,160.88 ; 131.852,160.652 132.157,160.652 ; 131.867,160.637 132.172,160.637 ; 131.883,160.621 132.187,160.621 ; 131.898,160.606 132.203,160.606 ; 131.913,160.591 132.218,160.591 ; 131.928,160.576 132.233,160.576 ; 131.944,160.56 132.248,160.56 ; 131.959,160.545 132.264,160.545 ; 131.974,160.53 132.279,160.53 ; 131.974,160.835 131.791,160.835 ; 131.989,160.515 132.294,160.515 ; 132.005,160.499 132.309,160.499 ; 132.005,160.804 131.771,160.804 ; 132.02,160.484 132.325,160.484 ; 132.02,160.789 131.766,160.789 ; 132.035,160.469 132.34,160.469 ; 132.05,160.454 132.355,160.454 ; 132.066,160.439 132.37,160.439 ; 132.081,160.423 132.386,160.423 ; 132.096,160.408 132.401,160.408 ; 132.111,160.393 132.416,160.393 ; 132.126,160.378 132.429,160.378 ; 132.142,160.362 132.444,160.362 ; 132.157,160.347 132.459,160.347 ; 132.172,160.332 132.474,160.332 ; 132.187,160.317 132.49,160.317 ; 132.203,160.301 132.505,160.301 ; 132.218,160.286 132.52,160.286 ; 132.233,160.271 132.535,160.271 ; 132.248,160.256 132.551,160.256 ; 132.261,160.24 132.566,160.24 ; 132.276,160.225 132.581,160.225 ; 132.292,160.21 132.596,160.21 ; 132.307,160.195 132.612,160.195 ; 132.322,160.179 132.627,160.179 ; 132.337,160.164 132.642,160.164 ; 132.353,160.149 132.657,160.149 ; 132.368,160.134 132.673,160.134 ; 132.383,160.118 132.688,160.118 ; 132.398,160.103 132.703,160.103 ; 132.414,160.088 132.718,160.088 ; 132.429,160.073 132.734,160.073 ; 132.444,160.058 132.749,160.058 ; 132.459,160.042 132.764,160.042 ; 132.474,160.027 132.779,160.027 ; 132.49,160.012 132.795,160.012 ; 132.505,159.997 132.81,159.997 ; 132.52,159.981 132.825,159.981 ; 132.535,159.966 132.84,159.966 ; 132.551,159.951 132.855,159.951 ; 132.566,159.936 132.871,159.936 ; 132.581,159.92 132.886,159.92 ; 132.596,159.905 132.894,159.905 ; 132.612,159.89 132.899,159.89 ; 132.627,159.875 132.901,159.875 ; 132.642,159.859 132.901,159.859 ; 132.657,159.844 132.896,159.844 ; 132.673,159.829 132.888,159.829 ; 132.688,159.814 132.878,159.814 ; 132.703,159.798 132.863,159.798 ; 132.718,159.783 132.848,159.783 ; 132.828,159.768 132.734,159.768 ; 131.766,160.789 131.771,160.804 ; 131.766,160.789 131.763,160.771 131.771,160.738 131.779,160.726 132.721,159.778 132.734,159.768 ; 131.771,160.804 131.791,160.835 ; 131.791,160.835 131.819,160.863 131.85,160.883 131.865,160.888 131.883,160.891 131.916,160.883 131.931,160.875 131.944,160.865 ; 131.944,160.865 132.886,159.918 132.894,159.905 ; 132.734,159.768 132.749,159.76 132.782,159.753 132.8,159.755 132.815,159.76 132.845,159.781 132.873,159.809 132.894,159.839 132.899,159.854 132.901,159.872 132.894,159.905
  Top Layer w0.203: 120.925,164.264 121.56,163.629 129.028,163.629 132.332,160.322
  Top Layer w0.635: pad.1@119.147,168.455 119.147,166.042 120.925,164.264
